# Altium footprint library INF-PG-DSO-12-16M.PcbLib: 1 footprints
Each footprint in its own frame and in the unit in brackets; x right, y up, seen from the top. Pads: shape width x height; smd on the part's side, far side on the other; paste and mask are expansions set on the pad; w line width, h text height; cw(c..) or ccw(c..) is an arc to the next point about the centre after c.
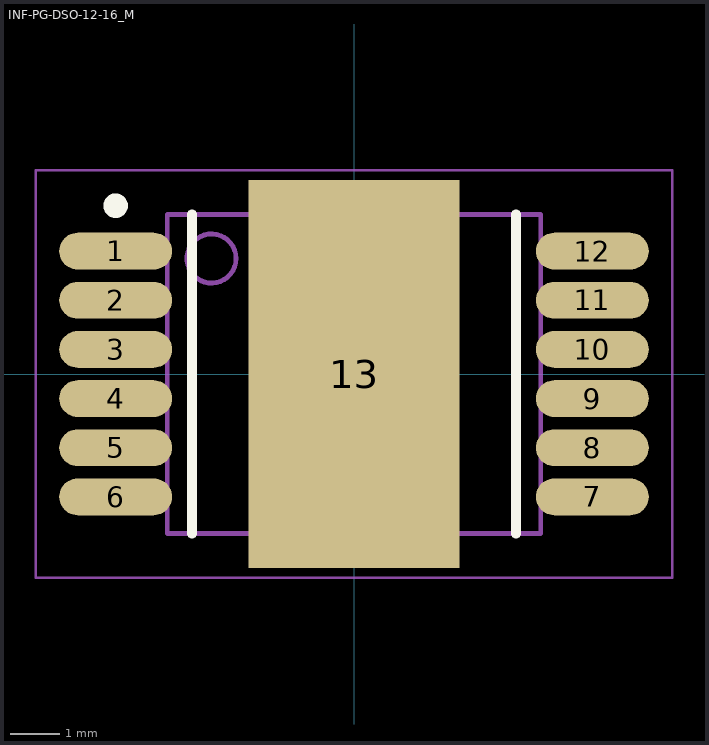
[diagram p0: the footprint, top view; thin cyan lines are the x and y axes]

## INF-PG-DSO-12-16_M [mm] "SOP, 12-Leads, Body 7.5x6.4mm, Pitch 1mm, Thermal Pad 4.3X7.9mm, IPC Low Density"
height 2.6
pads (13):
  oval 2.3x0.75 smd: 1(-4.85,2.5) 2(-4.85,1.5) 3(-4.85,0.5) 4(-4.85,-0.5) 5(-4.85,-1.5) 6(-4.85,-2.5) 7(4.85,-2.5) 8(4.85,-1.5) 9(4.85,-0.5) 10(4.85,0.5) 11(4.85,1.5) 12(4.85,2.5)
  rect 4.3x7.9 smd: 13(0,0)
Top Overlay:
  circle w0.25: c-4.85,3.425 r0.125
  lines w0.2: -3.3,-3.25 -3.3,3.25 ; 3.3,-3.25 3.3,3.25
Mechanical 13:
  circle w0.1: c-2.9,2.35 r0.5
  lines w0.1: -3.8,-3.25 -3.8,3.25 3.8,3.25 3.8,-3.25 -3.8,-3.25
Mechanical 15:
  lines w0.05: -6.475,-4.15 -6.475,4.15 6.475,4.15 6.475,-4.15 -6.475,-4.15
  lines w0.1: -0.5,0 0.5,0 ; 0,-0.5 0,0.5
3D body: height 2.6, standoff 0, extent -3.8,-3.25 3.8,3.25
